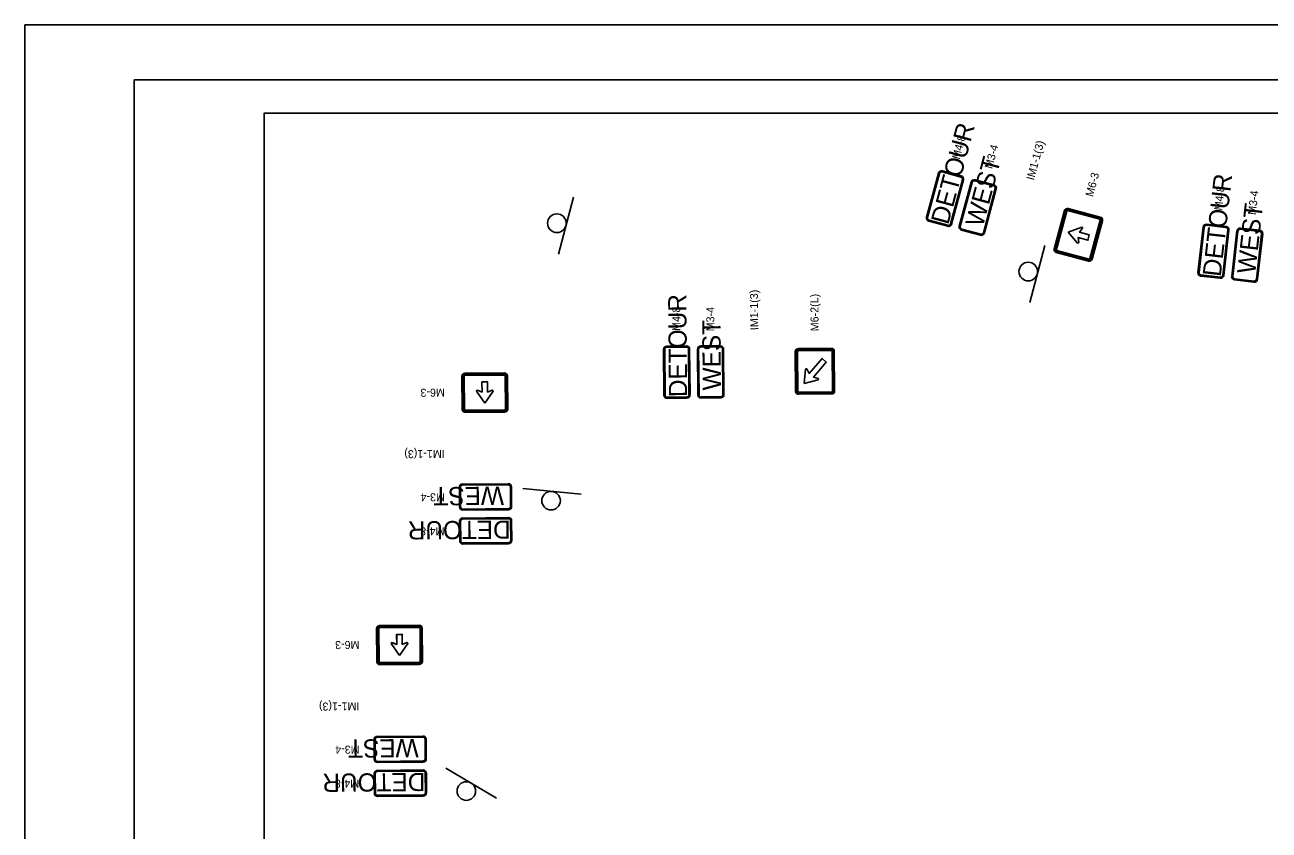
# Model space of a CAD drawing. Extents: x 2162123 to 2216123, y 180770 to 216770.
# Drawn here: x 2162123 to 2190113, y 198666 to 216770 of the extents above; entities that cross this region are included whole.
import ezdxf

# ---------------------------------------------------------------- set-up
doc = ezdxf.new("R2010")
doc.units = 0
for name, color, linetype in [('Default', 7, 'Continuous'), ('PR_Phasing_Detour_1', 7, 'Continuous'), ('SHT_Plot_Shape_Full', 7, 'Continuous'), ('SHT_Plot_Shape_Half', 7, 'Continuous'), ('SHT_Section_Layout_Block', 7, 'Continuous'), ('SHT_Sheet_Border', 7, 'Continuous')]:
    doc.layers.add(name, color=color, linetype=linetype)

# ---------------------------------------------------------------- blocks, each defined once
blk = doc.blocks.new('PRSIGN')
at = {"layer": 'Default'}
blk.add_line((20.04, 6.36), (-20.04, 6.36), dxfattribs=at)
blk.add_circle((0, 0), 6.35, dxfattribs=at)

msp = doc.modelspace()

# ---------------------------------------------------------------- linework, layer by layer
at = {"layer": 'PR_Phasing_Detour_1'}
for p, q in [((2182672, 213435), (2182405, 212445)), ((2182695, 213429), (2182429, 212438)), ((2183180, 213349), (2182755, 213463)), ((2183186, 213373), (2182762, 213487)), ((2182948, 212299), (2183214, 213289)), ((2183923, 213172), (2183498, 213286)), ((2182971, 212292), (2183238, 213283)), ((2183409, 213235), (2183142, 212244)), ((2183432, 213228), (2183166, 212238)), ((2183917, 213149), (2183492, 213263)), ((2183685, 212098), (2183951, 213089)), ((2183708, 212092), (2183975, 213082)), ((2185513, 212597), (2185280, 211732)), ((2185531, 212592), (2185298, 211727)), ((2185531, 212592), (2185298, 211727)), ((2185327, 211719), (2185560, 212584)), ((2185327, 211719), (2185560, 212584)), ((2185580, 212595), (2186303, 212401)), ((2185580, 212595), (2186303, 212401)), ((2186311, 212430), (2185588, 212625)), ((2186311, 212430), (2185588, 212625)), ((2186316, 212448), (2185593, 212643)), ((2182457, 212355), (2182882, 212241)), ((2182463, 212378), (2182888, 212264)), ((2183200, 212178), (2183625, 212064)), ((2185901, 212223), (2185591, 212112)), ((2185849, 212107), (2185916, 212197)), ((2186315, 212381), (2186082, 211516)), ((2186315, 212381), (2186082, 211516)), ((2186112, 211508), (2186344, 212373)), ((2186112, 211508), (2186344, 212373)), ((2186129, 211503), (2186362, 212368)), ((2188627, 212224), (2188512, 211205)), ((2188652, 212221), (2188536, 211202)), ((2189142, 212215), (2188706, 212264)), ((2189145, 212239), (2188708, 212288)), ((2189901, 212127), (2189464, 212176)), ((2189904, 212151), (2189467, 212200)), ((2183194, 212154), (2183619, 212040)), ((2185591, 212112), (2185804, 211861)), ((2185829, 211875), (2185816, 211987)), ((2185816, 211987), (2186035, 211928)), ((2186067, 212049), (2185849, 212107)), ((2186035, 211928), (2186067, 212049)), ((2189070, 211141), (2189185, 212161)), ((2189094, 211139), (2189210, 212158)), ((2189386, 212136), (2189271, 211117)), ((2189410, 212133), (2189295, 211114)), ((2189829, 211053), (2189944, 212073)), ((2189853, 211051), (2189968, 212070)), ((2185326, 211652), (2186050, 211458)), ((2185331, 211670), (2186054, 211475)), ((2185331, 211670), (2186054, 211475)), ((2186062, 211505), (2185339, 211699)), ((2186062, 211505), (2185339, 211699)), ((2188577, 211124), (2189013, 211074)), ((2188579, 211148), (2189016, 211098)), ((2189338, 211060), (2189775, 211010)), ((2189335, 211035), (2189772, 210986)), ((2176491, 209473), (2176499, 208448)), ((2176516, 209474), (2176524, 208448)), ((2177003, 209551), (2176564, 209547)), ((2177004, 209526), (2176564, 209523)), ((2177061, 208452), (2177053, 209478)), ((2177086, 208453), (2177077, 209478)), ((2177255, 209477), (2177263, 208452)), ((2177279, 209478), (2177288, 208452)), ((2177767, 209555), (2177328, 209551)), ((2177767, 209530), (2177328, 209527)), ((2177825, 208456), (2177817, 209482)), ((2177849, 208457), (2177841, 209482)), ((2179453, 209426), (2179460, 208530)), ((2179471, 209426), (2179479, 208530)), ((2179471, 209426), (2179479, 208530)), ((2179509, 208530), (2179502, 209426)), ((2179509, 208530), (2179502, 209426)), ((2180267, 209497), (2179517, 209491)), ((2180267, 209479), (2179518, 209473)), ((2180267, 209479), (2179518, 209473)), ((2179518, 209442), (2180267, 209448)), ((2179518, 209442), (2180267, 209448)), ((2180283, 209432), (2180291, 208537)), ((2180283, 209432), (2180291, 208537)), ((2180321, 208537), (2180314, 209433)), ((2180321, 208537), (2180314, 209433)), ((2180339, 208537), (2180332, 209433)), ((2171954, 208873), (2171960, 208123)), ((2171973, 208873), (2171979, 208124)), ((2171973, 208873), (2171979, 208124)), ((2172009, 208124), (2172003, 208873)), ((2172009, 208124), (2172003, 208873)), ((2172915, 208945), (2172019, 208938)), ((2172915, 208927), (2172019, 208920)), ((2172915, 208927), (2172019, 208920)), ((2172019, 208889), (2172915, 208896)), ((2172019, 208889), (2172915, 208896)), ((2172931, 208881), (2172937, 208131)), ((2172931, 208881), (2172937, 208131)), ((2172968, 208132), (2172962, 208881)), ((2172968, 208132), (2172962, 208881)), ((2172986, 208132), (2172980, 208881)), ((2179686, 209032), (2179651, 208705)), ((2172283, 208533), (2172472, 208264)), ((2172408, 208513), (2172303, 208554)), ((2172531, 208741), (2172406, 208740)), ((2172406, 208740), (2172408, 208513)), ((2172472, 208264), (2172657, 208536)), ((2172533, 208514), (2172531, 208741)), ((2172636, 208557), (2172533, 208514)), ((2179651, 208705), (2179970, 208787)), ((2176573, 208400), (2177013, 208403)), ((2176573, 208375), (2177013, 208379)), ((2177337, 208404), (2177776, 208407)), ((2177337, 208379), (2177777, 208383)), ((2180275, 208520), (2179525, 208514)), ((2180275, 208520), (2179525, 208514)), ((2179526, 208484), (2180275, 208490)), ((2179526, 208484), (2180275, 208490)), ((2179526, 208466), (2180275, 208472)), ((2172921, 208115), (2172026, 208108)), ((2172921, 208115), (2172026, 208108)), ((2172026, 208077), (2172922, 208085)), ((2172026, 208077), (2172922, 208085)), ((2172026, 208059), (2172922, 208066)), ((2171897, 206373), (2171900, 205934)), ((2171921, 206373), (2171925, 205934)), ((2172995, 206455), (2171970, 206447)), ((2172995, 206431), (2171970, 206423)), ((2173048, 205943), (2173045, 206382)), ((2173073, 205943), (2173069, 206383)), ((2171974, 205885), (2173000, 205894)), ((2171974, 205861), (2173000, 205869)), ((2171901, 205609), (2171904, 205170)), ((2171925, 205610), (2171929, 205170)), ((2172999, 205691), (2171974, 205683)), ((2172999, 205667), (2171974, 205659)), ((2173052, 205179), (2173049, 205619)), ((2173077, 205179), (2173073, 205619)), ((2171978, 205122), (2173004, 205130)), ((2171978, 205097), (2173004, 205105)), ((2170995, 203272), (2170099, 203264)), ((2170995, 203253), (2170100, 203246)), ((2170995, 203253), (2170100, 203246)), ((2170100, 203216), (2170996, 203223)), ((2170100, 203216), (2170996, 203223)), ((2171012, 203207), (2171018, 202458)), ((2171012, 203207), (2171018, 202458)), ((2171048, 202458), (2171042, 203207)), ((2171048, 202458), (2171042, 203207)), ((2171067, 202458), (2171061, 203207)), ((2170035, 203199), (2170041, 202450)), ((2170053, 203199), (2170059, 202450)), ((2170053, 203199), (2170059, 202450)), ((2170090, 202450), (2170084, 203199)), ((2170090, 202450), (2170084, 203199)), ((2170611, 203067), (2170487, 203066)), ((2170487, 203066), (2170488, 202840)), ((2170613, 202841), (2170611, 203067)), ((2170363, 202859), (2170553, 202590)), ((2170488, 202840), (2170384, 202880)), ((2170553, 202590), (2170738, 202862)), ((2170717, 202883), (2170613, 202841)), ((2171002, 202441), (2170106, 202434)), ((2171002, 202441), (2170106, 202434)), ((2170106, 202404), (2171002, 202411)), ((2170106, 202404), (2171002, 202411)), ((2170107, 202385), (2171002, 202393)), ((2169977, 200699), (2169981, 200260)), ((2170002, 200700), (2170005, 200260)), ((2171076, 200781), (2170050, 200773)), ((2171076, 200757), (2170050, 200749)), ((2171129, 200269), (2171125, 200709)), ((2171153, 200269), (2171150, 200709)), ((2170055, 200212), (2171080, 200220)), ((2170055, 200187), (2171080, 200195)), ((2169981, 199936), (2169985, 199496)), ((2170006, 199936), (2170009, 199496)), ((2171080, 200018), (2170054, 200010)), ((2171080, 199993), (2170054, 199985)), ((2171133, 199505), (2171129, 199945)), ((2171157, 199506), (2171154, 199945)), ((2170059, 199448), (2171084, 199456)), ((2170059, 199423), (2171084, 199432))]:
    msp.add_line(p, q, dxfattribs=at)
for points in [[(2185902, 212222), (2185592, 212112)], [(2185830, 211875), (2185817, 211987), (2186036, 211928), (2186068, 212048), (2185849, 212107), (2185917, 212197)], [(2185592, 212112), (2185805, 211861)], [(2179968, 208817), (2179862, 208853), (2180152, 209190), (2180058, 209271), (2179767, 208935), (2179715, 209034)], [(2179968, 208817), (2179862, 208853), (2180152, 209190), (2180058, 209271), (2179767, 208935), (2179715, 209034)], [(2179686, 209032), (2179651, 208705)], [(2172283, 208534), (2172472, 208265)], [(2172636, 208558), (2172533, 208515), (2172531, 208742), (2172406, 208741), (2172408, 208514), (2172303, 208555)], [(2172472, 208265), (2172657, 208537)], [(2179651, 208705), (2179970, 208787)], [(2170717, 202884), (2170613, 202841), (2170611, 203068), (2170486, 203067), (2170488, 202840), (2170384, 202881)], [(2170363, 202860), (2170553, 202591)], [(2170553, 202591), (2170738, 202863)]]:
    msp.add_lwpolyline(points, dxfattribs=at)
for centre, radius, start, end in [((2182743, 213416), 73.3, 74.946, 164.946), ((2182743, 213416), 48.8, 74.946, 164.946), ((2183167, 213302), 48.8, 344.946, 74.946), ((2183167, 213302), 73.3, 344.946, 74.946), ((2183479, 213216), 73.3, 74.946, 164.946), ((2183479, 213216), 48.8, 74.946, 164.946), ((2183904, 213101), 48.8, 344.946, 74.946), ((2183904, 213101), 73.3, 344.946, 74.946), ((2182476, 212426), 73.3, 164.946, 254.946), ((2185576, 212580), 64.9, 74.946, 164.946), ((2185576, 212580), 46.6, 74.946, 164.946), ((2185576, 212580), 46.6, 74.946, 164.946), ((2185576, 212580), 16.1, 74.946, 164.946), ((2185576, 212580), 16.1, 74.946, 164.946), ((2186299, 212385), 64.9, 344.946, 74.946), ((2182476, 212426), 48.8, 164.946, 254.946), ((2182901, 212311), 73.3, 254.946, 344.946), ((2182901, 212311), 48.8, 254.946, 344.946), ((2183213, 212225), 73.3, 164.946, 254.946), ((2183213, 212225), 48.8, 164.946, 254.946), ((2185896, 212202), 20.8, 344.946, 74.946), ((2185897, 212202), 20.8, 344.946, 74.946), ((2186299, 212385), 16.1, 344.946, 74.946), ((2186299, 212385), 16.1, 344.946, 74.946), ((2186299, 212385), 46.6, 344.946, 74.946), ((2186299, 212385), 46.6, 344.946, 74.946), ((2188700, 212215), 73.3, 83.5468, 173.5468), ((2188700, 212215), 48.8, 83.5468, 173.5468), ((2189137, 212166), 48.8, 353.5468, 83.5468), ((2189137, 212166), 73.3, 353.5468, 83.5468), ((2189459, 212127), 73.3, 83.5468, 173.5468), ((2189459, 212127), 48.8, 83.5468, 173.5468), ((2183638, 212111), 73.3, 254.946, 344.946), ((2183638, 212111), 48.8, 254.946, 344.946), ((2189896, 212078), 48.8, 353.5468, 83.5468), ((2189896, 212078), 73.3, 353.5468, 83.5468), ((2185343, 211715), 64.9, 164.946, 254.946), ((2185343, 211715), 46.6, 164.946, 254.946), ((2185343, 211715), 46.6, 164.946, 254.946), ((2185343, 211715), 16.1, 164.946, 254.946), ((2185343, 211715), 16.1, 164.946, 254.946), ((2185809, 211881), 20.8, 254.946, 344.946), ((2185810, 211881), 20.8, 254.946, 344.946), ((2186067, 211520), 64.9, 254.946, 344.946), ((2186067, 211520), 46.6, 254.946, 344.946), ((2186067, 211520), 46.6, 254.946, 344.946), ((2186067, 211520), 16.1, 254.946, 344.946), ((2186067, 211520), 16.1, 254.946, 344.946), ((2188585, 211196), 73.3, 173.5468, 263.5468), ((2188585, 211196), 48.8, 173.5468, 263.5468), ((2189022, 211147), 73.3, 263.5468, 353.5468), ((2189022, 211147), 48.8, 263.5468, 353.5468), ((2189343, 211108), 73.3, 173.5468, 263.5468), ((2189343, 211108), 48.8, 173.5468, 263.5468), ((2189780, 211059), 73.3, 263.5468, 353.5468), ((2189780, 211059), 48.8, 263.5468, 353.5468), ((2176564, 209474), 73.3, 90.4611, 180.4611), ((2176564, 209474), 48.8, 90.4611, 180.4611), ((2177004, 209478), 73.3, 0.4611, 90.4611), ((2177004, 209478), 48.8, 0.4611, 90.4611), ((2177328, 209478), 73.3, 90.4611, 180.4611), ((2177328, 209478), 48.8, 90.4611, 180.4611), ((2177768, 209482), 73.3, 0.4611, 90.4611), ((2177768, 209482), 48.8, 0.4611, 90.4611), ((2179518, 209426), 64.9, 90.4611, 180.4611), ((2179518, 209426), 46.6, 90.4611, 180.4611), ((2179518, 209426), 46.6, 90.4611, 180.4611), ((2179518, 209426), 16.1, 90.4611, 180.4611), ((2179518, 209426), 16.1, 90.4611, 180.4611), ((2180267, 209432), 64.9, 0.4611, 90.4611), ((2180267, 209432), 46.6, 0.4611, 90.4611), ((2180267, 209432), 46.6, 0.4611, 90.4611), ((2180267, 209432), 16.1, 0.4611, 90.4611), ((2180267, 209432), 16.1, 0.4611, 90.4611), ((2172019, 208873), 64.9, 90.4611, 180.4611), ((2172019, 208873), 46.6, 90.4611, 180.4611), ((2172019, 208873), 46.6, 90.4611, 180.4611), ((2172019, 208873), 16.1, 90.4611, 180.4611), ((2172019, 208873), 16.1, 90.4611, 180.4611), ((2172915, 208880), 64.9, 0.4611, 90.4611), ((2172915, 208880), 46.6, 0.4611, 90.4611), ((2172915, 208880), 46.6, 0.4611, 90.4611), ((2172915, 208880), 16.1, 0.4611, 90.4611), ((2172915, 208880), 16.1, 0.4611, 90.4611), ((2179702, 209018), 20.8, 49.2024, 139.2024), ((2179702, 209018), 20.8, 49.2024, 139.2024), ((2179954, 208801), 20.8, 319.2024, 49.2024), ((2179954, 208801), 20.8, 319.2024, 49.2024), ((2172304, 208534), 20.8, 90.4611, 180.4611), ((2172304, 208533), 20.8, 90.4611, 180.4611), ((2172637, 208537), 20.8, 0.4611, 90.4611), ((2172637, 208536), 20.8, 0.4611, 90.4611), ((2179525, 208531), 64.9, 180.4611, 270.4611), ((2179525, 208531), 46.6, 180.4611, 270.4611), ((2179525, 208531), 46.6, 180.4611, 270.4611), ((2179525, 208531), 16.1, 180.4611, 270.4611), ((2179525, 208531), 16.1, 180.4611, 270.4611), ((2180274, 208537), 64.9, 270.4611, 0.4611), ((2180274, 208537), 46.6, 270.4611, 0.4611), ((2180274, 208537), 16.1, 270.4611, 0.4611), ((2180274, 208537), 46.6, 270.4611, 0.4611), ((2180274, 208537), 16.1, 270.4611, 0.4611), ((2176573, 208448), 73.3, 180.4611, 270.4611), ((2176573, 208448), 48.8, 180.4611, 270.4611), ((2177012, 208452), 73.3, 270.4611, 0.4611), ((2177012, 208452), 48.8, 270.4611, 0.4611), ((2177336, 208452), 73.3, 180.4611, 270.4611), ((2177336, 208452), 48.8, 180.4611, 270.4611), ((2177776, 208456), 48.8, 270.4611, 0.4611), ((2177776, 208456), 73.3, 270.4611, 0.4611), ((2172025, 208124), 64.9, 180.4611, 270.4611), ((2172025, 208124), 46.6, 180.4611, 270.4611), ((2172025, 208124), 46.6, 180.4611, 270.4611), ((2172025, 208124), 16.1, 180.4611, 270.4611), ((2172025, 208124), 16.1, 180.4611, 270.4611), ((2172921, 208131), 16.1, 270.4611, 0.4611), ((2172921, 208131), 16.1, 270.4611, 0.4611), ((2172921, 208131), 64.9, 270.4611, 0.4611), ((2172921, 208131), 46.6, 270.4611, 0.4611), ((2172921, 208131), 46.6, 270.4611, 0.4611), ((2171970, 206374), 73.3, 90.4611, 180.4611), ((2171970, 206374), 48.8, 90.4611, 180.4611), ((2172996, 206382), 73.3, 0.4611, 90.4611), ((2172996, 206382), 48.8, 0.4611, 90.4611), ((2171974, 205934), 73.3, 180.4611, 270.4611), ((2171974, 205934), 48.8, 180.4611, 270.4611), ((2172999, 205942), 48.8, 270.4611, 0.4611), ((2172999, 205942), 73.3, 270.4611, 0.4611), ((2171974, 205610), 73.3, 90.4611, 180.4611), ((2171974, 205610), 48.8, 90.4611, 180.4611), ((2173000, 205618), 73.3, 0.4611, 90.4611), ((2173000, 205618), 48.8, 0.4611, 90.4611), ((2171978, 205170), 73.3, 180.4611, 270.4611), ((2171978, 205170), 48.8, 180.4611, 270.4611), ((2173003, 205179), 73.3, 270.4611, 0.4611), ((2173003, 205179), 48.8, 270.4611, 0.4611), ((2170100, 203199), 64.9, 90.4611, 180.4611), ((2170100, 203199), 46.6, 90.4611, 180.4611), ((2170100, 203199), 46.6, 90.4611, 180.4611), ((2170100, 203199), 16.1, 90.4611, 180.4611), ((2170100, 203199), 16.1, 90.4611, 180.4611), ((2170996, 203207), 64.9, 0.4611, 90.4611), ((2170996, 203207), 46.6, 0.4611, 90.4611), ((2170996, 203207), 46.6, 0.4611, 90.4611), ((2170996, 203207), 16.1, 0.4611, 90.4611), ((2170996, 203207), 16.1, 0.4611, 90.4611), ((2170384, 202860), 20.8, 90.4611, 180.4611), ((2170384, 202860), 20.8, 90.4611, 180.4611), ((2170717, 202863), 20.8, 0.4611, 90.4611), ((2170717, 202862), 20.8, 0.4611, 90.4611), ((2170106, 202450), 64.9, 180.4611, 270.4611), ((2170106, 202450), 46.6, 180.4611, 270.4611), ((2170106, 202450), 46.6, 180.4611, 270.4611), ((2170106, 202450), 16.1, 180.4611, 270.4611), ((2170106, 202450), 16.1, 180.4611, 270.4611), ((2171002, 202457), 64.9, 270.4611, 0.4611), ((2171002, 202457), 46.6, 270.4611, 0.4611), ((2171002, 202457), 16.1, 270.4611, 0.4611), ((2171002, 202457), 46.6, 270.4611, 0.4611), ((2171002, 202457), 16.1, 270.4611, 0.4611), ((2170051, 200700), 73.3, 90.4611, 180.4611), ((2170051, 200700), 48.8, 90.4611, 180.4611), ((2171076, 200708), 73.3, 0.4611, 90.4611), ((2171076, 200708), 48.8, 0.4611, 90.4611), ((2170054, 200260), 73.3, 180.4611, 270.4611), ((2170054, 200260), 48.8, 180.4611, 270.4611), ((2171080, 200269), 48.8, 270.4611, 0.4611), ((2171080, 200269), 73.3, 270.4611, 0.4611), ((2170055, 199936), 73.3, 90.4611, 180.4611), ((2170055, 199936), 48.8, 90.4611, 180.4611), ((2171080, 199945), 73.3, 0.4611, 90.4611), ((2171080, 199945), 48.8, 0.4611, 90.4611), ((2170058, 199497), 73.3, 180.4611, 270.4611), ((2170058, 199497), 48.8, 180.4611, 270.4611), ((2171084, 199505), 73.3, 270.4611, 0.4611), ((2171084, 199505), 48.8, 270.4611, 0.4611)]:
    msp.add_arc(centre, radius, start, end, dxfattribs=at)
at = {"layer": 'SHT_Plot_Shape_Full'}
msp.add_lwpolyline([(2162123, 216770), (2216123, 216770), (2216123, 180770), (2162123, 180770)], close=True, dxfattribs=at)
at = {"layer": 'SHT_Plot_Shape_Half'}
msp.add_lwpolyline([(2164579, 215532), (2215579, 215532), (2215579, 182532), (2164579, 182532)], close=True, dxfattribs=at)
at = {"layer": 'SHT_Section_Layout_Block'}
msp.add_lwpolyline([(2167504, 183282), (2167504, 214782), (2208387, 214782), (2208387, 211973), (2214628, 211973), (2214754, 185757), (2203354, 185757), (2203354, 183282)], close=True, dxfattribs=at)
at = {"layer": 'SHT_Sheet_Border'}
msp.add_lwpolyline([(2214754, 183282), (2167504, 183282), (2167504, 214782), (2214754, 214782)], close=True, dxfattribs=at)

# ---------------------------------------------------------------- block references
at = {"layer": 'PR_Phasing_Detour_1'}
for p, xscale, yscale, rotation in [((2174091, 212310), 32.99999999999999, 33.00000000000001, -104.78332417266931), ((2184695, 211224), 32.99999999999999, 33.00000000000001, -104.78332417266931), ((2173960, 206073), 32.99999999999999, 33.00000000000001, -5.478587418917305), ((2172054, 199544), 33, 32.99999999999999, -30.692614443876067)]:
    msp.add_blockref('PRSIGN', p, dxfattribs=dict(at, xscale=xscale, yscale=yscale, rotation=rotation))

# ---------------------------------------------------------------- texts
for s, height, rotation, p in [('DETOUR', 410.3, 74.946, (2182895, 212261)), ('M4-8', 180, 74.946, (2183149, 213735)), ('IM1-1(3)', 180, 74.946, (2184822, 213265)), ('M3-4', 180, 74.946, (2183883, 213521)), ('WEST', 410.3, 74.946, (2183671, 212204)), ('M6-3', 180, 74.946, (2186150, 212893)), ('DETOUR', 410.3, 83.5468, (2189024, 211096)), ('M4-8', 180, 83.5468, (2189054, 212591)), ('M3-4', 180, 83.5468, (2189812, 212490)), ('WEST', 410.3, 83.5468, (2189799, 211156)), ('IM1-1(3)', 180, 90.4611, (2178620, 209907)), ('DETOUR', 410.3, 90.4611, (2177021, 208402)), ('M6-2(L)', 180, 90.4611, (2179979, 209882)), ('M4-8', 180, 90.4611, (2176871, 209890)), ('M3-4', 180, 90.4611, (2177635, 209881)), ('WEST', 410.3, 90.4611, (2177783, 208554)), ('M6-3', 180, 180.4611, (2171570, 208593)), ('IM1-1(3)', 180, 180.4611, (2171567, 207214)), ('WEST', 410.3, 180.4611, (2172897, 206389)), ('M3-4', 180, 180.4611, (2171571, 206241)), ('DETOUR', 410.3, 180.4611, (2173050, 205627)), ('M4-8', 180, 180.4611, (2171562, 205477)), ('M6-3', 180, 180.4611, (2169650, 202920)), ('IM1-1(3)', 180, 180.4611, (2169647, 201540)), ('WEST', 410.3, 180.4611, (2170978, 200716)), ('M3-4', 180, 180.4611, (2169652, 200567)), ('DETOUR', 410.3, 180.4611, (2171130, 199953)), ('M4-8', 180, 180.4611, (2169642, 199803))]:
    msp.add_text(s, height=height, rotation=rotation, dxfattribs=at).set_placement(p)

doc.saveas('drawing.dxf')
